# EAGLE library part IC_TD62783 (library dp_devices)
8 Channel High voltage Source driver Mfr no: TD62783 TD62783AFG
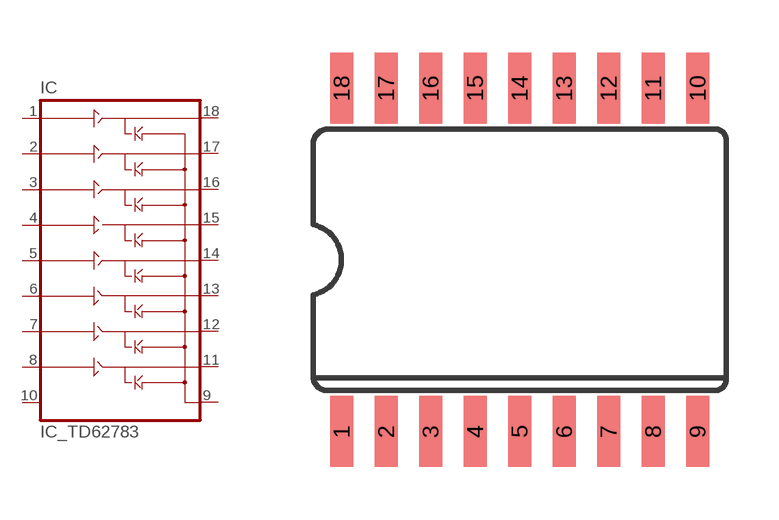
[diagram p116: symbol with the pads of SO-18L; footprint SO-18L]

Designator prefix IC

## IC_TD62783-SO-18W  [SO-18L]
1  IN1  in
2  IN2  in
3  IN3  in
4  IN4  in
5  IN5  in
6  IN6  in
7  IN7  in
8  IN8  in
9  GND  pwr
10  VS  pwr
11  OUT8  out
12  OUT7  out
13  OUT6  out
14  OUT5  out
15  OUT4  out
16  OUT3  out
17  OUT2  out
18  OUT1  out

## Footprint SO-18L (pad centres in mm)
smd 0.66 x 2.032: 1 -4.445,-4.902; 2 -3.175,-4.902; 3 -1.905,-4.902; 4 -0.635,-4.902; 5 0.635,-4.902; 6 1.905,-4.902; 7 3.175,-4.902; 8 4.445,-4.902; 9 5.715,-4.902; 10 5.715,4.902; 11 4.445,4.902; 12 3.175,4.902; 13 1.905,4.902; 14 0.635,4.902; 15 -0.635,4.902; 16 -1.905,4.902; 17 -3.175,4.902; 18 -4.445,4.902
